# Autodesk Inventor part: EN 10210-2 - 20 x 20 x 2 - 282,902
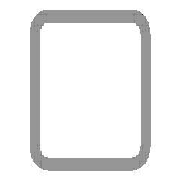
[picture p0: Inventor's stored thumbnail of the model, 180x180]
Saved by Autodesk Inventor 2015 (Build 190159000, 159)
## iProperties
_CCFamilyMember: 1
_CCFamilyDisplayName: DIN EN 10210-2 (Square) - Tube
_FrameMemberDoc: Frame Member File
_Version: 15.0.0
_GetPNFromCC: 1
Created: 2015-05
Part Number: EN 10210-2 - 20 x 20 x 2 - 282,902
Material: Steel, Mild
Description: Tube
Document SubType Name: Modeling
Standard: DIN
Designer: TREINA6
Standard Revision: 1997
Standards Organization: DIN
Language: en-US
Size Designation: 20 x 20 x 2
Categories: <MemberInstance><Categories><Category DisplayName="Structural Shapes" InternalName="089c4875-fa83-4c05-b084-43b9cc11f5ed" Mnemonic="GRDR"><CategoryParameter Dis
Stock Number: 20 x 20 x 2
Density: 7.85 g/cm^3
Appearance: Semi-Polished
IsCustomPart: 1
G_L: 282,902 mm
G_W: 20,000 mm
G_H: 20,000 mm
+E0A39B40-F93E-43A3-86F3-37080D4D8280+CUTDETAIL1: Miter 60,00 deg
+074C0221-DC1C-46C6-AC78-E21AE067C0E7+CUTDETAIL2: Miter 60,00 deg
Author: TREINA6
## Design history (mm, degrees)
node "Start plane"
node "End plane"
sketch "Sketch"
  geometry: L1 (-10, -7)-(-10, 7); L2 (-7, 10)-(7, 10); L3 (10, 7)-(10, -7); L4 (7, -10)-(-7, -10); L5 (-7, 8)-(7, 8); L6 (8, 7)-(8, -7); L7 (7, -8)-(-7, -8); L8 (-8, -7)-(-8, 7); L9 (0, 14.87)-(0, -14.87) reference; L10 (-14.87, 0)-(14.87, 0) reference; A1 r 3 centre (-7, -7) between (-10, -7) and (-7, -10); A2 r 3 centre (-7, 7) between (-7, 10) and (-10, 7); A3 r 3 centre (7, 7) between (10, 7) and (7, 10); A4 r 3 centre (7, -7) between (7, -10) and (10, -7); A5 r 1 centre (-7, 7) between (-7, 8) and (-8, 7); A6 r 1 centre (7, 7) between (8, 7) and (7, 8); A7 r 1 centre (7, -7) between (7, -8) and (8, -7); A8 r 1 centre (-7, -7) between (-8, -7) and (-7, -8)
  constraints: 16 end point, 16 point on circle, 8 centre point, 8 tangent, 4 parallel, 3 equal radius, 2 perpendicular, 7 other
  dimensions: "d7" = 3 radius of A1 (= G_IR); "d10" = 20 distance between parallel lines of L2 L4 (= G_H); "d11" = 20 distance between parallel lines of L1 L3 (= G_W); "d12" = 2 distance between parallel lines of L3 L6 (= G_T); "d15" = 10 distance between parallel lines of L2 L10 (= 0.5 x d10); "d16" = 10 distance between parallel lines of L9 L3 (= 0.5 x d11)
extrude "Body" new body sketch "Sketch" stored distance "d3" = 282.90163 (= G_L); taper "d4" = 0 deg
node "Driven Length"
  sketch "Sketch3"
    geometry: L1 (0, 0)-(10, 0) reference
    constraints: 2 end point, 1 horizontal
  workplane "Work Plane3"
  sketch "Sketch4"
    geometry: L1 (-2, 0)-(12, 0) reference; L2 (-2, 282.902)-(12, 282.902) reference
    dimensions: "d18" = 282.90163 distance between parallel lines of L1 L2 (derived)
workplane "Work Plane4"
split "Split1"
workplane "Work Plane5"
split "Split2"
body "Solid1"
other parameters: "G_W" = 20 [user parameter; used in 1 equation term], "G_H" = 20 [user parameter; used in 1 equation term], "G_T" = 2 [user parameter; used in 1 equation term], "G_IR" = 3 [user parameter; used in 1 equation term], "G_L" = 282.90163 (= d18) [user parameter; used in 1 equation term], "G_OFFSET_START" = 0 [user parameter; used in 1 equation term], "G_OFFSET_END" = 0 [user parameter; used in 1 equation term], "d13" = 0 (computed from G_OFFSET_START), "d14" = 282.90163 (= G_OFFSET_END + B_L), "B_L" = 282.90163 [user parameter; used in 1 equation term], "d17" = 90 deg
